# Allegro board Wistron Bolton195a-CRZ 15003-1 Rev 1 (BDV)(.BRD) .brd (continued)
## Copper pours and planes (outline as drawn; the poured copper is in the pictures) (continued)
HDMI_DP_5V on TOP: 130.43,106.38 130.02,106.78 130.02,109.91 130.05,109.93 131.39,109.93 132,109.32 132.51,109.32 132.56,109.27 132.56,108.36 133.2,107.72 133.2,106.48 133.1,106.38 ; 1 cut-out
ISW_1 on TOP: 46.99,9.6 46.71,9.88 46.71,12.65 46.84,12.78 49.89,12.78 50.19,12.47 50.19,10.01 49.78,9.6
ISW_1 on BOTTOM: 45.92,9.4 45.59,9.73 45.59,12.57 45.78,12.76 49.89,12.76 50.16,12.48 50.16,9.6 49.96,9.4
LCD_BOOST_VOUT on TOP: 29.95,2.84 29.24,3.56 29.24,8.76 29.29,8.81 30.71,8.81 30.84,8.69 30.84,7.29 31.01,7.11 41.73,7.11 42.16,6.68 42.16,3.66 41.35,2.84
LCD_BOOST_VOUT on BOTTOM: 35.66,3.86 35.31,4.22 35.31,6.27 35.61,6.58 38.81,6.58 40.03,7.8 41.71,7.8 42.49,7.01 42.49,4.88 41.48,3.86
LEDGND on TOP: 25.93,15.52 25.68,15.77 25.68,20.4 25.43,20.65 24,20.65 23.37,20.02 23.37,19.46 23.09,19.18 20.62,19.18 20.45,19.35 20.45,20.85 22.73,23.14 24.71,23.14 28.41,19.44 28.41,15.86 28.07,15.52
LEDGND on BOTTOM: 25.3,7.9 23.47,9.73 23.47,11.58 23.57,11.68 24.51,11.68 24.71,11.89 25.73,11.89 26.01,11.61 29.16,11.61 30.02,12.47 30.4,12.47 30.43,12.45 30.43,11.86 28.47,9.91 27.86,9.91 27.69,9.73 27.69,8.2 27.38,7.9 ; 7 cut-outs
LX on TOP: 45.49,4.32 44.91,4.9 44.91,8.15 45.36,8.61 49.99,8.61 50.75,9.37 50.75,16.48 51.18,16.92 58.55,16.92 58.62,16.84 58.62,4.5 58.45,4.32
LX on BOTTOM: 44.93,4.37 44.35,4.95 44.35,7.95 45.01,8.61 52.17,8.61 52.58,9.02 52.58,13.72 53.02,14.16 58.1,14.16 58.67,13.59 58.67,4.57 58.47,4.37
MCT1 on TOP: 128.14,47.45 128.12,47.47 128.12,48.08 131.04,48.08 131.19,47.93 131.19,47.62 131.01,47.45
MCT1 on TOP: 130.56,56.52 130.33,56.74 130.33,60.5 130.51,60.68 131.42,60.68 131.83,60.27 131.83,56.74 131.6,56.52 ; 2 cut-outs
MCT1 on TOP: 128.14,53.39 128.12,53.42 128.12,54.03 131.04,54.03 131.19,53.87 131.19,53.57 131.01,53.39
MCT1 on TOP: 128.14,44.48 128.12,44.5 128.12,45.11 131.04,45.11 131.19,44.96 131.19,44.65 131.01,44.48
MCT1 on TOP: 128.14,50.42 128.12,50.44 128.12,51.05 131.04,51.05 131.19,50.9 131.19,50.6 131.01,50.42
MCT1 on BOTTOM: 130.48,44.3 130.2,44.58 130.2,57.63 129.64,58.19 127.15,58.19 126.92,58.42 126.92,60.76 127.08,60.91 131.17,60.91 131.78,60.3 131.78,44.5 131.57,44.3
MCT_R on TOP: 127.89,58.52 127.81,58.6 127.81,61.29 127.94,61.42 129.74,61.42 129.82,61.34 129.82,58.75 129.59,58.52 ; 1 cut-out
P_1.05VLAN_OUT on BOTTOM: 113.46,64.19 113.41,64.24 113.41,64.87 114.96,66.42 114.96,69.85 114.66,70.15 114.66,70.99 115.29,71.63 116.92,71.63 116.97,71.58 116.97,65.89 115.27,64.19
PWR_1D8V on TOP: 24.2,129.63 23.54,130.29 23.54,136.29 24.09,136.83 28.21,136.83 28.44,136.6 28.44,133.2 28.14,132.89 28.14,129.82 27.94,129.63 ; 5 cut-outs
PWR_1D8V_PH on TOP: 16.66,130.98 16.26,131.38 16.26,135.26 16.31,135.31 17.6,135.31 18.27,135.97 20.29,135.97 20.94,135.32 20.94,131.37 20.55,130.98
PWR_1D8V_PVIN on TOP: 10.35,130.78 9.81,131.32 9.81,134.61 10.07,134.88 12.13,134.88 12.2,134.81 14.05,134.81 14.09,134.77 14.09,130.96 13.91,130.78 ; 5 cut-outs
PWR_3D3V on TOP: 80.67,13.69 79.07,15.29 70.08,15.29 69.7,15.67 69.7,23.74 69.93,23.97 72.64,23.97 72.64,23.98 73.27,23.98 75.35,21.89 82.33,21.89 85.42,18.81 85.42,14.76 84.35,13.69 ; 4 cut-outs
PWR_3D3V_PH on TOP: 88.03,10.99 87.91,11.11 87.91,12.27 87.25,12.93 87.25,19.15 87.58,19.48 92.14,19.48 92.34,19.28 92.34,16.98 92.33,16.96 91.25,16.96 91.21,16.93 91.21,15.49 91.22,15.48 91.22,15 91.49,14.73 94.04,14.73 94.17,14.61 94.17,11.28 93.89,10.99 ; 1 cut-out
PWR_5V on TOP: 87.68,35.41 87.12,35.97 87.12,44.7 87.44,45.02 91.59,45.02 93.67,42.95 93.67,41.09 94.96,39.8 94.96,35.71 94.65,35.41 ; 2 cut-outs
PWR_5V_PH on TOP: 88.84,26.38 88.63,26.59 88.63,28.34 87.91,29.06 87.07,29.06 86.91,29.22 86.91,33.23 87.48,33.79 96.99,33.79 97.84,32.94 97.84,28.37 97.65,28.18 94.47,28.18 94.44,28.21 94.44,29.28 94.28,29.45 92.56,29.45 92.36,29.25 92.36,26.45 92.29,26.38 ; 1 cut-out
PWR_AD+_2 on TOP: 116.71,17.91 116.59,18.03 116.59,19.81 116.97,20.19 117.47,20.19 119.89,22.61 121.79,22.61 121.92,22.48 121.92,21.46 121.54,21.08 120.14,21.08 119.89,20.83 119.89,20.45 119.76,20.32 119.13,20.32 118.62,19.81 118.62,18.03 118.49,17.91 ; 2 cut-outs
PWR_CORE_PH1 on TOP: 51.18,184.43 49.28,186.33 49.29,186.35 49.29,188.56 49.59,188.86 63.5,188.86 63.8,188.56 63.8,187.75 63.8,187.74 63.8,184.95 63.4,184.56 54.86,184.56 54.74,184.43
PWR_CORE_PH1 on BOTTOM: 51.13,184.43 49.03,186.54 49.03,190.01 49.03,190.02 49.03,190.14 48.97,190.2 48.13,190.2 48.01,190.32 48.01,190.9 48.08,190.98 48.79,190.98 48.92,191.11 48.92,191.39 49.35,191.82 61.44,191.82 61.54,191.72 61.54,191.15 61.76,190.93 64.36,190.93 64.43,190.87 64.43,185.55 63.31,184.43
PWR_CORE_VIN on BOTTOM: 70.13,184.91 68.77,186.27 65.11,186.27 64.76,186.63 64.76,194.4 65.91,195.55 70.23,195.55 72.29,193.5 72.29,193.04 72.28,193.03 72.28,185.1 72.09,184.91 ; 2 cut-outs
PWR_DCBATOUT_5V3D3V on TOP: 96.03,15.87 96.02,15.88 93.08,15.88 92.95,16.01 92.95,19.13 93.29,19.47 93.29,27.58 93.42,27.71 98.02,27.71 99.33,26.4 99.33,16.38 98.82,15.87 ; 2 cut-outs
PWR_DCBATOUT_5V3D3V on BOTTOM: 95.49,16.42 94.6,17.31 94.6,19.58 93.75,20.44 93.75,25.91 94.33,26.49 98.53,26.49 98.88,26.14 98.88,20.55 99.43,20 99.43,16.93 98.92,16.42 ; 2 cut-outs
PWR_DCBATOUT_VDDP on TOP: 12.99,125.67 12.98,125.68 10.84,125.68 10.36,126.16 10.36,129.16 10.67,129.46 12.57,129.46 12.98,129.06 15.85,129.06 15.88,129.03 15.88,125.73 15.82,125.68 13,125.68 ; 2 cut-outs
PWR_DCBATOUT_VDDP on BOTTOM: 12.3,125.59 11.89,126.01 11.89,129.23 12.06,129.41 14.5,129.41 15.02,128.9 15.02,125.68 14.93,125.59
PWR_DCBATOUT_VDDQ on BOTTOM: 115.74,127.16 115.11,127.79 115.11,140.16 119.53,140.16 119.73,139.96 119.73,127.88 119.01,127.16 ; 2 cut-outs
PWR_VDDNB_PH on TOP: 11.48,171.7 10.74,172.44 10.74,176.58 11.02,176.86 14.66,176.86 14.73,176.78 14.73,175.41 14.99,175.16 16.92,175.16 17.46,175.7 17.46,180.68 17.5,180.72 22.91,180.72 23,180.63 23,175.02 19.68,171.7
PWR_VDDNB_VIN on TOP: 10.97,177.16 10.87,177.27 10.87,182.65 11.1,182.88 12.04,182.88 12.22,183.06 12.22,184.48 11.81,184.89 11.81,188.14 15.95,192.28 19.68,192.28 19.94,192.02 19.94,189.23 18.41,187.71 18.41,184.02 18.16,183.77 17.68,183.77 16.38,182.47 16.38,177.16 ; 2 cut-outs
PWR_VDDP on TOP: 24.37,117.06 23.97,117.46 23.97,127.74 24.19,127.96 28.06,127.96 28.35,127.67 29.08,127.67 29.54,127.21 29.54,126.48 30.02,126 30.02,117.19 29.88,117.06 ; 2 cut-outs
PWR_VDDP_PH on TOP: 14.73,121.28 14.71,121.31 14.71,124.56 14.81,124.66 16.23,124.66 16.46,124.89 16.46,127.8 16.56,127.9 17.9,127.9 18.65,128.65 20.7,128.65 20.98,128.38 20.98,121.81 20.45,121.28
PWR_VDDQ on BOTTOM: 104.66,145.3 104.38,145.58 104.38,153.13 104.63,153.39 117.48,153.39 118.21,152.66 118.21,148.12 117.25,147.16 111.71,147.16 109.85,145.3 ; 4 cut-outs
PWR_VDDQ_PH on BOTTOM: 110.16,138.96 109.78,139.34 109.78,144.37 111.48,146.08 117.46,146.08 117.9,145.64 117.9,142.42 117.35,141.86 117.35,140.77 117.32,140.74 114.68,140.74 114.07,140.13 114.07,138.96
PWR_VDDQ_VTTOUT on BOTTOM: 107.61,113.58 107.53,113.65 107.53,114.98 107.73,115.18 110.03,115.18 110.62,115.77 110.62,117.95 110.75,118.07 110.75,119.26 110.84,119.35 111.41,119.35 111.68,119.63 111.68,120.39 111.68,120.39 111.68,120.93 111.69,120.95 112.49,120.95 112.68,120.76 112.68,115.27 113.04,114.91 113.04,113.77 112.85,113.58
USB30_VCCA on TOP: 132.55,174.66 132.27,174.94 132.27,178.44 132.53,178.69 136.54,178.69 136.92,178.31 136.92,175.85 137.01,175.76 137.01,175.03 136.64,174.66 ; 3 cut-outs
USB30_VCCA on TOP: 136.91,72.82 136.42,73.3 136.42,83.59 136.07,83.95 134.8,83.95 134.7,84.05 134.7,84.61 134.82,84.73 136.09,84.73 137.52,86.16 137.52,89.97 139.67,92.13 139.67,96.49 138.76,97.41 137.79,97.41 137.29,97.92 137.29,99.57 138.51,100.79 143.99,100.79 146.25,98.53 146.25,87.1 143.87,84.71 140.46,84.71 139.78,84.02 139.78,73.41 139.19,72.82 ; 5 cut-outs
USB30_VCCA on BOTTOM: 85.75,61.67 85.65,61.77 85.65,65.52 86.08,65.95 89.14,65.95 98.68,75.49 106.45,75.49 112.17,81.2 124.42,81.2 126.24,79.39 139.15,79.39 139.6,78.94 139.6,73.15 139.22,72.77 126.7,72.77 122.63,76.83 113.63,76.83 108.76,71.96 100.54,71.96 90.25,61.67 ; 6 cut-outs
V_3_CARD on TOP: 129.49,143.59 129.21,143.87 129.21,145.41 129.29,145.49 133.58,145.49 133.71,145.36 133.71,144.4 133.58,144.27 131.32,144.27 131.22,144.17 131.22,143.79 131.01,143.59
V_3_CARD on BOTTOM: 132.79,142.65 132.69,142.75 132.69,143.26 132.36,143.59 130.76,143.59 130.51,143.84 130.51,145.54 130.81,145.85 134.42,145.85 134.54,145.72 134.54,144.96 133.96,144.37 133.96,142.77 133.83,142.65 ; 7 cut-outs
V_3P3_LAN on TOP: 100.58,57.02 100.37,57.24 100.37,59.07 100.99,59.69 105.92,59.69 106.3,60.07 106.3,62.56 106.45,62.71 108.1,62.71 109.6,61.21 113.03,61.21 113.54,61.72 113.54,62.94 113.23,63.25 113.23,65.84 113.41,66.01 114.22,66.01 114.55,65.68 114.55,60.38 114.27,60.1 108.56,60.1 108.46,59.99 108.46,57.53 108.2,57.28 104.01,57.28 103.76,57.02 ; 15 cut-outs
V_5_CODEC on TOP: 120.12,33.88 120.09,33.91 120.09,34.87 120.14,34.92 121.16,34.92 121.92,35.69 121.92,35.71 123.04,36.83 123.04,37.49 123.27,37.72 124.13,37.72 124.36,37.95 125.76,37.95 126.06,37.64 126.06,36.04 125.45,35.43 123.19,35.43 122.81,35.05 122.43,35.05 121.26,33.88 ; 1 cut-out
V_5_CODEC on TOP: 114.05,33.4 112.14,35.31 108.97,35.31 108.84,35.43 108.84,36.32 109.35,36.83 111.68,36.83 112.19,36.32 113.67,36.32 114.25,35.74 114.25,33.48 114.17,33.4 ; 5 cut-outs
V_5_LCD1 on BOTTOM: 9.15,111.17 8.96,111.36 8.96,113.7 9.41,114.15 10.88,114.15 10.96,114.07 10.96,113.36 10.74,113.15 10.74,111.3 10.61,111.17 ; 1 cut-out
V_5_ODD on TOP: 8.54,61.39 8.43,61.5 8.43,64.8 8.57,64.94 11.58,64.94 12.45,64.06 12.45,61.53 12.32,61.39
V_5_ODD on BOTTOM: 6.74,60.74 6.53,60.96 6.53,64.69 6.77,64.94 11.58,64.94 12.45,64.06 12.45,61.13 12.06,60.74 ; 2 cut-outs
XRF_TDC1 on TOP: 117.81,53.39 117.68,53.52 117.68,53.9 117.81,54.03 120.9,54.03 120.9,53.42 120.88,53.39
XRF_TDC1 on TOP: 116.79,44.48 116.66,44.6 116.66,45.09 116.69,45.11 120.9,45.11 120.9,44.5 120.88,44.48
XRF_TDC1 on TOP: 117.81,47.45 117.68,47.57 117.68,47.96 117.81,48.08 120.9,48.08 120.9,47.47 120.88,47.45
XRF_TDC1 on TOP: 117.83,50.42 117.64,50.61 116.8,50.61 116.71,50.7 116.71,51.21 116.76,51.26 117.96,51.26 118.16,51.05 120.88,51.05 120.88,50.44 120.85,50.42
XRF_TDC1 on BOTTOM: 117.7,44.48 117.22,44.96 117.22,53.98 117.47,54.23 118.29,54.23 118.49,54.03 118.49,44.7 118.26,44.48

Small or netless copper shapes (teardrops, artwork), in the pictures only: 5 on TOP, 7 on BOTTOM

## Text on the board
Ref Des/Silkscreen Bottom: X3:25MHZ | F7:2A/6V | F4:2A/6V | X1:32.768KHZ | F6:1.1A/6V
Ref Des/Assembly Top: SATA1 | SATA0
Ref Des/Silkscreen Top: F9:1.1A/6V | F1:1.5A/24V | X2:48MHZ | F3:1.1A/6V | F8:1.1A/6V | PACRZL/Bolton195a-CRZ | 15003-1 | 348.04301.0011 | MADE IN TAIWAN
User.22: 0 | 47 | 276 | 374 | 79 | 39 | 35 | 51 | 20 | 354
User.23: 0 | 150
User.24: Board Accuracy Check,Jun 10 16:42:48 2015,Passed | Dummy-Static-No Shape On Layer Check,Jun 10 16:42:48 2015,Passed | Split Plane Check,Jun 08 11:30:34 2015,Passed
User.27: ByImpedance:100.0@_REF_L1=("4.0/12.0(L1)")|Type="DP"|_REF_L4=("4.0/12.0(L4)")|_REF_L3=("nil(L3)")|imp="100.0" | ByImpedance:32.0@_REF_L1=("9.5(L1)")|Type="SE"|_REF_L4=("9.5(L4)")|_REF_L3=("9.0(L3)")|imp="32.0" | ByImpedance:34.0@_REF_L1=("9.0(L1)")|Type="SE"|_REF_L4=("9.0(L4)")|_REF_L3=("8.0(L3)")|imp="34.0" | ByImpedance:35.0@_REF_L1=("8.5(L1)")|Type="SE"|_REF_L4=("8.5(L4)")|_REF_L3=("7.5(L3)")|imp="35.0" | ByImpedance:37.5@_REF_L1=("7.5(L1)")|Type="SE"|_REF_L4=("7.5(L4)")|_REF_L3=("7.0(L3)")|imp="37.5" | ByImpedance:39.0@_REF_L1=("7.0(L1)")|Type="SE"|_REF_L4=("7.0(L4)")|_REF_L3=("6.5(L3)")|imp="39.0" | ByImpedance:40.0@_REF_L1=("6.5(L1)")|Type="SE"|_REF_L4=("6.5(L4)")|_REF_L3=("6.0(L3)")|imp="40.0" | ByImpedance:42.0@_REF_L1=("6.0(L1)")|Type="SE"|_REF_L4=("6.0(L4)")|_REF_L3=("5.5(L3)")|imp="42.0" | ByImpedance:45.0@_REF_L1=("5.0(L1)")|Type="SE"|_REF_L4=("5.0(L4)")|_REF_L3=("4.5(L3)")|imp="45.0" | ByImpedance:50.0@_REF_L1=("4.0(L1)")|Type="SE"|_REF_L4=("4.0(L4)")|_REF_L3=("4.0(L3)")|imp="50.0" | ByImpedance:62.0@_REF_L1=("8.5/5.0(L1)")|Type="DP"|_REF_L4=("8.5/5.0(L4)")|_REF_L3=("7.5/5.0(L3)")|imp="62.0" | ByImpedance:65.0@_REF_L1=("8.0/5.0(L1)")|Type="DP"|_REF_L4=("8.0/5.0(L4)")|_REF_L3=("7.0/5.5(L3)")|imp="65.0" | ByImpedance:70.0@_REF_L1=("7.0/5.0(L1)")|Type="DP"|_REF_L4=("7.0/5.0(L4)")|_REF_L3=("6.0/5.0(L3)")|imp="70.0" | ByImpedance:72.0@_REF_L1=("7.0/7.0(L1)")|Type="DP"|_REF_L4=("7.0/7.0(L4)")|_REF_L3=("5.5/5.0(L3)")|imp="72.0" | ByImpedance:80.0@_REF_L1=("6.0/9.0(L1)" "5.0/5.0(L1)")|Type="DP"|_REF_L4=("6.0/9.0(L4)" "5.0/5.0(L4)")|_REF_L3=("4.5/6.0(L3)")|imp="80.0" | ByImpedance:85.0@_REF_L1=("4.0/4.5(L1)" "5.0/7.0(L1)")|Type="DP"|_REF_L4=("4.0/4.5(L4)" "5.0/7.0(L4)")|_REF_L3=("4.0/6.0(L3)")|imp="85.0" | ByImpedance:90.0@_REF_L1=("4.0/6.0(L1)")|Type="DP"|_REF_L4=("4.0/6.0(L4)")|_REF_L3=("4.0/9.0(L3)")|imp="90.0" | ByImpedance:95.0@_REF_L1=("4.0/8.0(L1)")|Type="DP"|_REF_L4=("4.0/8.0(L4)")|_REF_L3=("nil(L3)")|imp="95.0" | LayerIndex:nil | Source:4-1.6-8d.xls | artWorks:("_REF_L3" "_REF_L4" "_REF_L1") | gtImpOutlineUsed:BOARD GEOMETRY/PANEL_OUTLINE
User.33: This gerber is just for your reference to find the DP impedance traces in layer L1. | DP IMPEDANCE TABLE: L1 | * - Denotes that WIDTH | is NOT used in this layer | inside board outline. | IMP(Ohm) | 62.0 | 65.0 | 70.0 | 72.0 | 80.0 | 85.0 | 90.0 | 95.0 | 100.0 | WIDTH(mils) | *8.5/5.0 | *8.0/5.0 | *7.0/5.0 | 7.0/7.0 | *6.0/9.0 | 5.0/5.0 | *4.0/4.5 | 5.0/7.0 | 4.0/6.0 | 4.0/8.0 | 4.0/12.0 | TYPE | DP
User.35: This gerber is just for your reference to find the SE impedance traces in layer L1. | SE IMPEDANCE TABLE: L1 | * - Denotes that WIDTH | is NOT used in this layer | inside board outline. | IMP(Ohm) | 32.0 | 34.0 | 35.0 | 37.5 | 39.0 | 40.0 | 42.0 | 45.0 | 50.0 | WIDTH(mils) | *9.5 | *9.0 | *8.5 | *7.5 | *7.0 | 6.5 | 6.0 | 5.0 | 4.0 | TYPE | SE
User.37: This gerber is just for your reference to find the DP impedance traces in layer L3. | DP IMPEDANCE TABLE: L3 | * - Denotes that WIDTH | is NOT used in this layer | inside board outline. | IMP(Ohm) | 62.0 | 65.0 | 70.0 | 72.0 | 80.0 | 85.0 | 90.0 | 95.0 | 100.0 | WIDTH(mils) | *7.5/5.0 | *7.0/5.5 | *6.0/5.0 | 5.5/5.0 | 4.5/6.0 | *4.0/6.0 | *4.0/9.0 | *nil | TYPE | DP
User.39: This gerber is just for your reference to find the SE impedance traces in layer L3. | SE IMPEDANCE TABLE: L3 | * - Denotes that WIDTH | is NOT used in this layer | inside board outline. | IMP(Ohm) | 32.0 | 34.0 | 35.0 | 37.5 | 39.0 | 40.0 | 42.0 | 45.0 | 50.0 | WIDTH(mils) | *9.0 | *8.0 | *7.5 | *7.0 | *6.5 | 6.0 | *5.5 | *4.5 | 4.0 | TYPE | SE
User.41: This gerber is just for your reference to find the DP impedance traces in layer L4. | DP IMPEDANCE TABLE: L4 | * - Denotes that WIDTH | is NOT used in this layer | inside board outline. | IMP(Ohm) | 62.0 | 65.0 | 70.0 | 72.0 | 80.0 | 85.0 | 90.0 | 95.0 | 100.0 | WIDTH(mils) | *8.5/5.0 | *8.0/5.0 | *7.0/5.0 | *7.0/7.0 | *6.0/9.0 | *5.0/5.0 | *4.0/4.5 | 5.0/7.0 | 4.0/6.0 | *4.0/8.0 | 4.0/12.0 | TYPE | DP
User.43: This gerber is just for your reference to find the SE impedance traces in layer L4. | SE IMPEDANCE TABLE: L4 | * - Denotes that WIDTH | is NOT used in this layer | inside board outline. | IMP(Ohm) | 32.0 | 34.0 | 35.0 | 37.5 | 39.0 | 40.0 | 42.0 | 45.0 | 50.0 | WIDTH(mils) | *9.5 | *9.0 | *8.5 | *7.5 | *7.0 | 6.5 | *6.0 | 5.0 | *4.0 | TYPE | SE
User.45: Note:Refer to DRILL layer for ELLIPSE drill direction | FIGURE | SIZE | 10.0 | 12.0 | 16.0 | 20.0 | 28.0 | 30.0 | 36.0 | 37.0 | 44.0 | 109.0 | 113.0 | 128.0 | 42.0 | 46.0 | 50.0 | 54.0 | 65.0 | 67.0 | 86.0 | 95.0 | 158.0 | 71.0x28.0 | 79.0x40.0 | 83.0x36.0 | 91.0x40.0 | 95.0x24.0 | 95.0x40.0 | 98.0x32.0 | 102.0x28.0 | 107.0x36.0 | DRILL CHART: TOP to BOTTOM | ALL UNITS ARE IN MILS | PLATED | NON-PLATED | QTY | 1344 | 644 | 666 | 40 | 9 | 29 | 8 | 6 | 1 | 2 | 3 | 4 | 5 | Model | PACRZL/Bolton195a-CRZ | PCB_NO | 15003 | VER. | Layer | DRILL | L1 | L2VCC | TMASK | TPLACE | TSILK | TSMD | Designer | MOSSE | Date | 07/29/2015 | BMASK | BPLACE | BSILK | BSMD | L3 | L4
